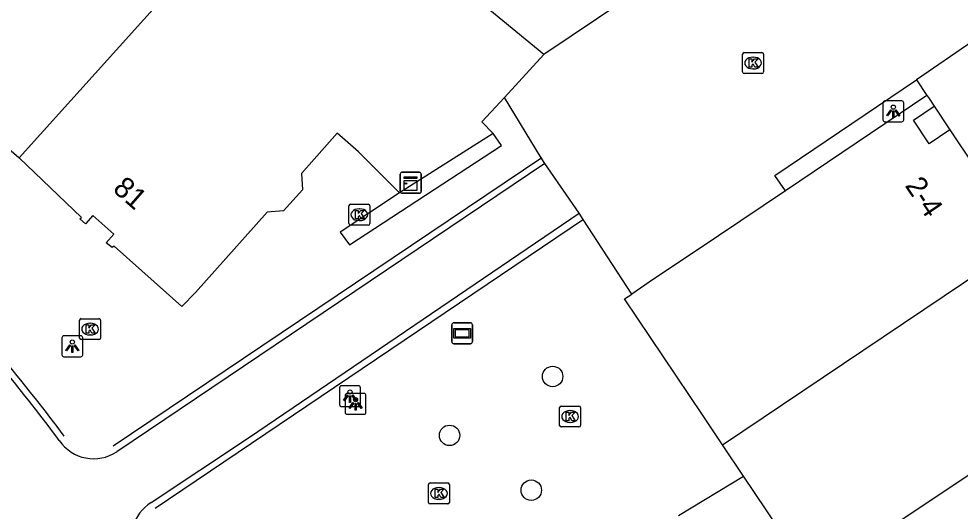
# Model space of a CAD drawing. Extents: x 161087 to 161922, y 382574 to 383873.
# Drawn here: x 161637.33 to 161682.36, y 382995.4 to 383018.93 of the extents above; entities that cross this region are included whole.
import ezdxf

# ---------------------------------------------------------------- set-up
doc = ezdxf.new("R2010")
doc.units = 0
for name, color, linetype in [('IMGEO_Boom', 7, 'Continuous'), ('IMGEO_Kast', 7, 'Continuous'), ('IMGEO_Kolk', 7, 'Continuous'), ('IMGEO_Lichtpunt', 7, 'Continuous'), ('IMGEO_Lijnafwatering', 7, 'Continuous'), ('IMGEO_Pand', 7, 'Continuous'), ('IMGEO_Pand_nummerreeks', 7, 'Continuous'), ('IMGEO_Reclamebord', 7, 'Continuous'), ('IMGEO_Rijbaan_lokaal_open', 7, 'Continuous'), ('IMGEO_Voetgangersgebied_gesloten', 7, 'Continuous'), ('IMGEO_Voetgangersgebied_open', 7, 'Continuous')]:
    doc.layers.add(name, color=color, linetype=linetype)

msp = doc.modelspace()

# ---------------------------------------------------------------- linework, layer by layer
at = {"layer": 'IMGEO_Boom'}
for centre in [(161662.868, 383001.84), (161657.937, 382999.025), (161661.846, 382996.403)]:
    msp.add_circle(centre, 0.489, dxfattribs=at)
at = {"layer": 'IMGEO_Kast'}
for p, q in [((161655.653, 383011.598), (161656.494, 383011.598)), ((161656.494, 383011.598), (161655.653, 383011.598)), ((161655.578, 383010.673), (161655.578, 383011.514)), ((161655.578, 383011.514), (161655.578, 383010.673)), ((161656.578, 383011.523), (161656.578, 383010.682)), ((161656.578, 383010.682), (161656.578, 383011.523)), ((161656.503, 383010.598), (161655.662, 383010.598)), ((161655.662, 383010.598), (161656.503, 383010.598))]:
    msp.add_line(p, q, dxfattribs=at)
for points in [[(161655.773, 383011.388), (161656.373, 383011.388), (161656.373, 383011.303), (161655.773, 383011.303), (161655.773, 383011.388)], [(161655.773, 383011.213), (161656.373, 383011.213), (161656.373, 383010.724), (161655.773, 383010.724), (161655.773, 383011.213)]]:
    msp.add_lwpolyline(points, dxfattribs=at)
msp.add_circle((161655.857, 383011.062), 0.0377, dxfattribs=at)
for centre, start, end in [((161655.656, 383011.52), 92.4484, 184.2845), ((161655.656, 383011.52), 92.4484, 184.2845), ((161656.5, 383011.52), 2.4484, 94.2845), ((161656.5, 383011.52), 2.4484, 94.2845), ((161655.656, 383010.676), 182.4484, 274.2845), ((161655.656, 383010.676), 182.4484, 274.2845), ((161656.5, 383010.676), 272.4484, 4.2845), ((161656.5, 383010.676), 272.4484, 4.2845)]:
    msp.add_arc(centre, 0.0779, start, end, dxfattribs=at)
at = {"layer": 'IMGEO_Kolk'}
for p, q in [((161671.954, 383016.393), (161671.954, 383017.245)), ((161672.029, 383017.319), (161672.881, 383017.319)), ((161672.442, 383017.099), (161672.467, 383017.099)), ((161672.955, 383017.245), (161672.955, 383016.393)), ((161672.881, 383016.319), (161672.029, 383016.319)), ((161672.465, 383016.539), (161672.44, 383016.539)), ((161653.12, 383009.145), (161653.12, 383009.997)), ((161653.195, 383010.071), (161654.047, 383010.071)), ((161653.608, 383009.851), (161653.633, 383009.851)), ((161654.121, 383009.997), (161654.121, 383009.145)), ((161654.047, 383009.071), (161653.195, 383009.071)), ((161653.631, 383009.291), (161653.606, 383009.291)), ((161640.239, 383003.676), (161640.239, 383004.528)), ((161640.314, 383004.602), (161641.166, 383004.602)), ((161641.24, 383004.528), (161641.24, 383003.676)), ((161640.727, 383004.382), (161640.752, 383004.382)), ((161641.166, 383003.602), (161640.314, 383003.602)), ((161640.75, 383003.822), (161640.725, 383003.822)), ((161663.2, 382999.501), (161663.2, 383000.353)), ((161663.275, 383000.427), (161664.127, 383000.427)), ((161664.201, 383000.353), (161664.201, 382999.501)), ((161663.688, 383000.207), (161663.713, 383000.207)), ((161663.711, 382999.647), (161663.686, 382999.647)), ((161664.127, 382999.427), (161663.275, 382999.427)), ((161657.004, 382996.75), (161657.856, 382996.75)), ((161656.929, 382995.824), (161656.929, 382996.676)), ((161657.417, 382996.53), (161657.442, 382996.53)), ((161657.93, 382996.676), (161657.93, 382995.824)), ((161657.44, 382995.97), (161657.415, 382995.97)), ((161657.856, 382995.75), (161657.004, 382995.75))]:
    msp.add_line(p, q, dxfattribs=at)
for points in [[(161671.954, 383016.393), (161671.954, 383017.245)], [(161672.029, 383017.319), (161672.881, 383017.319)], [(161672.275, 383017.019), (161672.398, 383017.019), (161672.398, 383016.868), (161672.528, 383017.019), (161672.692, 383017.019), (161672.546, 383016.868), (161672.699, 383016.619), (161672.547, 383016.619), (161672.462, 383016.783), (161672.398, 383016.716), (161672.398, 383016.619), (161672.275, 383016.619), (161672.275, 383017.019)], [(161672.955, 383017.245), (161672.955, 383016.393)], [(161672.881, 383016.319), (161672.029, 383016.319)], [(161653.12, 383009.145), (161653.12, 383009.997)], [(161653.195, 383010.071), (161654.047, 383010.071)], [(161654.121, 383009.997), (161654.121, 383009.145)], [(161653.441, 383009.771), (161653.564, 383009.771), (161653.564, 383009.62), (161653.694, 383009.771), (161653.858, 383009.771), (161653.712, 383009.62), (161653.865, 383009.371), (161653.713, 383009.371), (161653.628, 383009.535), (161653.564, 383009.468), (161653.564, 383009.371), (161653.441, 383009.371), (161653.441, 383009.771)], [(161654.047, 383009.071), (161653.195, 383009.071)], [(161640.239, 383003.676), (161640.239, 383004.528)], [(161640.314, 383004.602), (161641.166, 383004.602)], [(161641.24, 383004.528), (161641.24, 383003.676)], [(161640.56, 383004.302), (161640.683, 383004.302), (161640.683, 383004.151), (161640.813, 383004.302), (161640.977, 383004.302), (161640.831, 383004.151), (161640.984, 383003.902), (161640.832, 383003.902), (161640.747, 383004.066), (161640.683, 383003.999), (161640.683, 383003.902), (161640.56, 383003.902), (161640.56, 383004.302)], [(161641.166, 383003.602), (161640.314, 383003.602)], [(161663.2, 382999.501), (161663.2, 383000.353)], [(161663.275, 383000.427), (161664.127, 383000.427)], [(161664.201, 383000.353), (161664.201, 382999.501)], [(161663.521, 383000.127), (161663.644, 383000.127), (161663.644, 382999.976), (161663.774, 383000.127), (161663.938, 383000.127), (161663.792, 382999.976), (161663.945, 382999.727), (161663.793, 382999.727), (161663.708, 382999.891), (161663.644, 382999.824), (161663.644, 382999.727), (161663.521, 382999.727), (161663.521, 383000.127)], [(161664.127, 382999.427), (161663.275, 382999.427)], [(161657.004, 382996.75), (161657.856, 382996.75)], [(161656.929, 382995.824), (161656.929, 382996.676)], [(161657.25, 382996.45), (161657.373, 382996.45), (161657.373, 382996.299), (161657.503, 382996.45), (161657.667, 382996.45), (161657.521, 382996.299), (161657.674, 382996.05), (161657.522, 382996.05), (161657.437, 382996.214), (161657.373, 382996.147), (161657.373, 382996.05), (161657.25, 382996.05), (161657.25, 382996.45)], [(161657.93, 382996.676), (161657.93, 382995.824)], [(161657.856, 382995.75), (161657.004, 382995.75)]]:
    msp.add_lwpolyline(points, dxfattribs=at)
for centre, start, end in [((161672.031, 383017.243), 91.552, 178.448), ((161672.031, 383017.243), 91.552, 178.448), ((161672.879, 383017.243), 1.552, 88.448), ((161672.879, 383017.243), 1.552, 88.448), ((161672.031, 383016.395), 181.552, 268.448), ((161672.031, 383016.395), 181.552, 268.448), ((161672.879, 383016.395), 271.552, 358.448), ((161672.879, 383016.395), 271.552, 358.448), ((161653.197, 383009.995), 91.552, 178.448), ((161653.197, 383009.995), 91.552, 178.448), ((161654.045, 383009.995), 1.552, 88.448), ((161654.045, 383009.995), 1.552, 88.448), ((161653.197, 383009.147), 181.552, 268.448), ((161653.197, 383009.147), 181.552, 268.448), ((161654.045, 383009.147), 271.552, 358.448), ((161654.045, 383009.147), 271.552, 358.448), ((161640.316, 383004.526), 91.552, 178.448), ((161640.316, 383004.526), 91.552, 178.448), ((161641.164, 383004.526), 1.552, 88.448), ((161641.164, 383004.526), 1.552, 88.448), ((161640.316, 383003.678), 181.552, 268.448), ((161640.316, 383003.678), 181.552, 268.448), ((161641.164, 383003.678), 271.552, 358.448), ((161641.164, 383003.678), 271.552, 358.448), ((161663.277, 383000.351), 91.552, 178.448), ((161663.277, 383000.351), 91.552, 178.448), ((161664.125, 383000.351), 1.552, 88.448), ((161664.125, 383000.351), 1.552, 88.448), ((161663.277, 382999.503), 181.552, 268.448), ((161663.277, 382999.503), 181.552, 268.448), ((161664.125, 382999.503), 271.552, 358.448), ((161664.125, 382999.503), 271.552, 358.448), ((161657.006, 382996.674), 91.552, 178.448), ((161657.006, 382996.674), 91.552, 178.448), ((161657.854, 382996.674), 1.552, 88.448), ((161657.854, 382996.674), 1.552, 88.448), ((161657.006, 382995.826), 181.552, 268.448), ((161657.006, 382995.826), 181.552, 268.448), ((161657.854, 382995.826), 271.552, 358.448), ((161657.854, 382995.826), 271.552, 358.448)]:
    msp.add_arc(centre, 0.0765, start, end, dxfattribs=at)
for centre, major_axis, ratio, start_param, end_param in [((161672.441, 383016.819), (-0.387, 0.002), 0.722429, 4.712389, 7.853982), ((161672.466, 383016.819), (-0.39, 0.002), 0.717154, 1.570796, 4.712389), ((161653.607, 383009.571), (-0.387, 0.002), 0.722429, 4.712389, 7.853982), ((161653.632, 383009.571), (-0.39, 0.002), 0.717154, 1.570796, 4.712389), ((161640.726, 383004.102), (-0.387, 0.002), 0.722429, 4.712389, 7.853982), ((161640.751, 383004.102), (-0.39, 0.002), 0.717154, 1.570796, 4.712389), ((161663.687, 382999.927), (-0.387, 0.002), 0.722429, 4.712389, 7.853982), ((161663.712, 382999.927), (-0.39, 0.002), 0.717154, 1.570796, 4.712389), ((161657.416, 382996.25), (-0.387, 0.002), 0.722429, 4.712389, 7.853982), ((161657.441, 382996.25), (-0.39, 0.002), 0.717154, 1.570796, 4.712389)]:
    msp.add_ellipse(centre, major_axis=major_axis, ratio=ratio, start_param=start_param, end_param=end_param, dxfattribs=at)
at = {"layer": 'IMGEO_Lichtpunt'}
for p, q in [((161678.666, 383014.914), (161678.666, 383014.107)), ((161678.666, 383014.914), (161678.666, 383014.107)), ((161679.568, 383015.009), (161678.76, 383015.009)), ((161679.568, 383015.009), (161678.76, 383015.009)), ((161679.662, 383014.107), (161679.662, 383014.914)), ((161679.662, 383014.107), (161679.662, 383014.914)), ((161678.76, 383014.013), (161679.568, 383014.013)), ((161678.76, 383014.013), (161679.568, 383014.013)), ((161639.392, 383003.687), (161639.392, 383002.88)), ((161639.392, 383003.687), (161639.392, 383002.88)), ((161640.294, 383003.782), (161639.486, 383003.782)), ((161640.294, 383003.782), (161639.486, 383003.782)), ((161640.388, 383002.88), (161640.388, 383003.687)), ((161640.388, 383002.88), (161640.388, 383003.687)), ((161639.486, 383002.786), (161640.294, 383002.786)), ((161639.486, 383002.786), (161640.294, 383002.786)), ((161652.678, 383001.302), (161652.678, 383000.495)), ((161652.678, 383001.302), (161652.678, 383000.495)), ((161653.58, 383001.397), (161652.772, 383001.397)), ((161653.58, 383001.397), (161652.772, 383001.397)), ((161653.674, 383000.495), (161653.674, 383001.302)), ((161653.674, 383000.495), (161653.674, 383001.302)), ((161652.942, 383000.932), (161652.942, 383000.125)), ((161652.942, 383000.932), (161652.942, 383000.125)), ((161653.844, 383001.027), (161653.036, 383001.027)), ((161653.844, 383001.027), (161653.036, 383001.027)), ((161653.938, 383000.125), (161653.938, 383000.932)), ((161653.938, 383000.125), (161653.938, 383000.932)), ((161652.772, 383000.401), (161653.58, 383000.401)), ((161652.772, 383000.401), (161653.58, 383000.401)), ((161653.036, 383000.031), (161653.844, 383000.031)), ((161653.036, 383000.031), (161653.844, 383000.031))]:
    msp.add_line(p, q, dxfattribs=at)
for points in [[(161679.04, 383014.578), (161679.079, 383014.55), (161678.891, 383014.288), (161678.853, 383014.315), (161679.04, 383014.578)], [(161679.142, 383014.53), (161679.189, 383014.53), (161679.189, 383014.208), (161679.142, 383014.208), (161679.142, 383014.53)], [(161679.252, 383014.55), (161679.29, 383014.577), (161679.477, 383014.315), (161679.438, 383014.287), (161679.252, 383014.55)], [(161639.766, 383003.351), (161639.805, 383003.323), (161639.617, 383003.061), (161639.579, 383003.088), (161639.766, 383003.351)], [(161639.868, 383003.303), (161639.915, 383003.303), (161639.915, 383002.981), (161639.868, 383002.981), (161639.868, 383003.303)], [(161639.978, 383003.323), (161640.016, 383003.35), (161640.203, 383003.088), (161640.164, 383003.06), (161639.978, 383003.323)], [(161653.052, 383000.966), (161653.091, 383000.938), (161652.903, 383000.676), (161652.865, 383000.703), (161653.052, 383000.966)], [(161653.154, 383000.918), (161653.201, 383000.918), (161653.201, 383000.596), (161653.154, 383000.596), (161653.154, 383000.918)], [(161653.264, 383000.938), (161653.302, 383000.965), (161653.489, 383000.703), (161653.45, 383000.675), (161653.264, 383000.938)], [(161653.316, 383000.596), (161653.355, 383000.568), (161653.167, 383000.306), (161653.129, 383000.333), (161653.316, 383000.596)], [(161653.418, 383000.548), (161653.465, 383000.548), (161653.465, 383000.226), (161653.418, 383000.226), (161653.418, 383000.548)], [(161653.528, 383000.568), (161653.566, 383000.595), (161653.753, 383000.333), (161653.714, 383000.305), (161653.528, 383000.568)]]:
    msp.add_lwpolyline(points, dxfattribs=at)
for centre in [(161679.165, 383014.712), (161639.891, 383003.485), (161653.177, 383001.1), (161653.441, 383000.73)]:
    msp.add_circle(centre, 0.0994, dxfattribs=at)
for centre, start, end in [((161678.76, 383014.914), 90, 180), ((161678.76, 383014.914), 90, 180), ((161679.568, 383014.914), 0, 90), ((161679.568, 383014.914), 0, 90), ((161678.76, 383014.107), 180, 270), ((161678.76, 383014.107), 180, 270), ((161679.568, 383014.107), 270, 0), ((161679.568, 383014.107), 270, 360), ((161639.486, 383003.687), 90, 180), ((161639.486, 383003.687), 90, 180), ((161640.294, 383003.687), 0, 90), ((161640.294, 383003.687), 0, 90), ((161639.486, 383002.88), 180, 270), ((161639.486, 383002.88), 180, 270), ((161640.294, 383002.88), 270, 0), ((161640.294, 383002.88), 270, 360), ((161652.772, 383001.302), 90, 180), ((161652.772, 383001.302), 90, 180), ((161653.58, 383001.302), 0, 90), ((161653.58, 383001.302), 0, 90), ((161653.036, 383000.932), 90, 180), ((161653.036, 383000.932), 90, 180), ((161653.844, 383000.932), 0, 90), ((161653.844, 383000.932), 0, 90), ((161652.772, 383000.495), 180, 270), ((161652.772, 383000.495), 180, 270), ((161653.58, 383000.495), 270, 0), ((161653.58, 383000.495), 270, 360), ((161653.036, 383000.125), 180, 270), ((161653.036, 383000.125), 180, 270), ((161653.844, 383000.125), 270, 0), ((161653.844, 383000.125), 270, 360)]:
    msp.add_arc(centre, 0.0946, start, end, dxfattribs=at)
at = {"layer": 'IMGEO_Lijnafwatering'}
for points in [[(161641.85, 382998.522), (161662.345, 383012.299)], [(161643.848, 382995.547), (161664.342, 383009.361)]]:
    msp.add_lwpolyline(points, dxfattribs=at)
msp.add_arc((161571.231, 382948.219), 85.079, 36.64081, 42.69607, dxfattribs=at)
at = {"layer": 'IMGEO_Pand'}
for points in [[(161650.586, 383026.982), (161637.344, 383012.284)], [(161662.454, 383017.231), (161650.586, 383026.982)], [(161660.559, 383015.174), (161662.454, 383017.231)], [(161637.344, 383012.284), (161637.333, 383012.295), (161635.168, 383014.151), (161634.604, 383014.423), (161634.582, 383014.346), (161633.431, 383014.957), (161633.451, 383014.988), (161632.905, 383015.281), (161632.857, 383015.192), (161630.82, 383016.229)], [(161680.775, 383015.268), (161674.004, 383010.717)], [(161680.775, 383015.268), (161680.84, 383015.17), (161681.117, 383014.751)], [(161660.559, 383015.174), (161659.478, 383014.001), (161660.02, 383013.453)], [(161681.875, 383013.627), (161680.886, 383012.965), (161680.123, 383014.096), (161681.117, 383014.751)], [(161655.544, 383010.618), (161653.573, 383012.57), (161652.566, 383013.472), (161650.857, 383011.543), (161650.897, 383010.766), (161649.986, 383009.76), (161649.211, 383009.688), (161645.784, 383005.848), (161645.131, 383005.176), (161641.889, 383008.073), (161641.789, 383008), (161641.505, 383008.226), (161641.884, 383008.642), (161640.87, 383009.533), (161640.52, 383009.135), (161640.254, 383009.369), (161640.329, 383009.433), (161637.344, 383012.284)], [(161660.02, 383013.453), (161655.544, 383010.618)], [(161681.875, 383013.627), (161685.461, 383008.279)], [(161674.004, 383010.717), (161670.801, 383008.564), (161667.49, 383006.339), (161666.657, 383005.779)], [(161670.999, 382998.574), (161684.473, 383007.616)], [(161670.999, 382998.574), (161670.04, 383000), (161666.311, 383005.546), (161666.657, 383005.779)], [(161688.822, 383001.157), (161675.318, 382992.15)], [(161672.003, 382997.08), (161670.999, 382998.574)], [(161675.318, 382992.15), (161672.003, 382997.08)]]:
    msp.add_lwpolyline(points, dxfattribs=at)
at = {"layer": 'IMGEO_Reclamebord'}
for p, q in [((161658.143, 383004.404), (161658.933, 383004.404)), ((161658.933, 383004.404), (161658.143, 383004.404)), ((161658.043, 383003.504), (161658.043, 383004.304)), ((161658.043, 383004.304), (161658.043, 383003.504)), ((161659.033, 383004.304), (161659.033, 383003.504)), ((161659.033, 383003.504), (161659.033, 383004.304)), ((161658.933, 383003.404), (161658.143, 383003.404)), ((161658.143, 383003.404), (161658.933, 383003.404))]:
    msp.add_line(p, q, dxfattribs=at)
for points in [[(161658.144, 383004.136), (161658.932, 383004.136), (161658.932, 383003.672), (161658.144, 383003.672), (161658.144, 383004.136)], [(161658.209, 383004.071), (161658.209, 383003.737), (161658.867, 383003.737), (161658.867, 383004.071), (161658.209, 383004.071)]]:
    msp.add_lwpolyline(points, dxfattribs=at)
for centre, start, end in [((161658.143, 383004.304), 90, 180), ((161658.143, 383004.304), 90, 180), ((161658.933, 383004.304), 0, 90), ((161658.933, 383004.304), 360, 90), ((161658.143, 383003.504), 180, 270), ((161658.143, 383003.504), 180, 270), ((161658.933, 383003.504), 270, 0), ((161658.933, 383003.504), 270, 0)]:
    msp.add_arc(centre, 0.1, start, end, dxfattribs=at)
at = {"layer": 'IMGEO_Rijbaan_lokaal_open'}
for points in [[(161668.892, 383021.561), (161662.454, 383017.231)], [(161688.351, 383021.57), (161680.278, 383016.018)], [(161674.004, 383010.717), (161673.496, 383011.45), (161680.278, 383016.018)], [(161680.278, 383016.018), (161680.775, 383015.268)], [(161662.492, 383012.013), (161662.32, 383012.295), (161660.559, 383015.174)], [(161681.117, 383014.751), (161681.875, 383013.627)], [(161664.14, 383009.646), (161662.492, 383012.013)], [(161666.657, 383005.779), (161664.334, 383009.348), (161664.14, 383009.646)]]:
    msp.add_lwpolyline(points, dxfattribs=at)
at = {"layer": 'IMGEO_Voetgangersgebied_gesloten'}
for points in [[(161662.492, 383012.013), (161642.024, 382998.245)], [(161643.67, 382995.817), (161648.36, 382998.939), (161664.14, 383009.646)]]:
    msp.add_lwpolyline(points, dxfattribs=at)
for centre, radius, start, end in [((161577.584, 382953.191), 76.699, 36.46871, 42.90917), ((161640.914, 382999.904), 1.996, 214.2606, 303.799), ((161644.686, 382994.149), 1.953, 121.3499, 209.7305)]:
    msp.add_arc(centre, radius, start, end, dxfattribs=at)
at = {"layer": 'IMGEO_Voetgangersgebied_open'}
for points in [[(161655.544, 383010.618), (161652.703, 383008.729), (161653.15, 383008.125), (161660.428, 383012.88), (161660.02, 383013.453)], [(161668.885, 382995.196), (161672.003, 382997.08)]]:
    msp.add_lwpolyline(points, dxfattribs=at)

# ---------------------------------------------------------------- texts
at = {"layer": 'IMGEO_Pand_nummerreeks'}
for s, rotation, p in [('81', 318.6955, (161641.778, 383010.731)), ('2-4', 303.81, (161679.696, 383010.962))]:
    msp.add_text(s, height=1, rotation=rotation, dxfattribs=at).set_placement(p)

doc.saveas('drawing.dxf')
